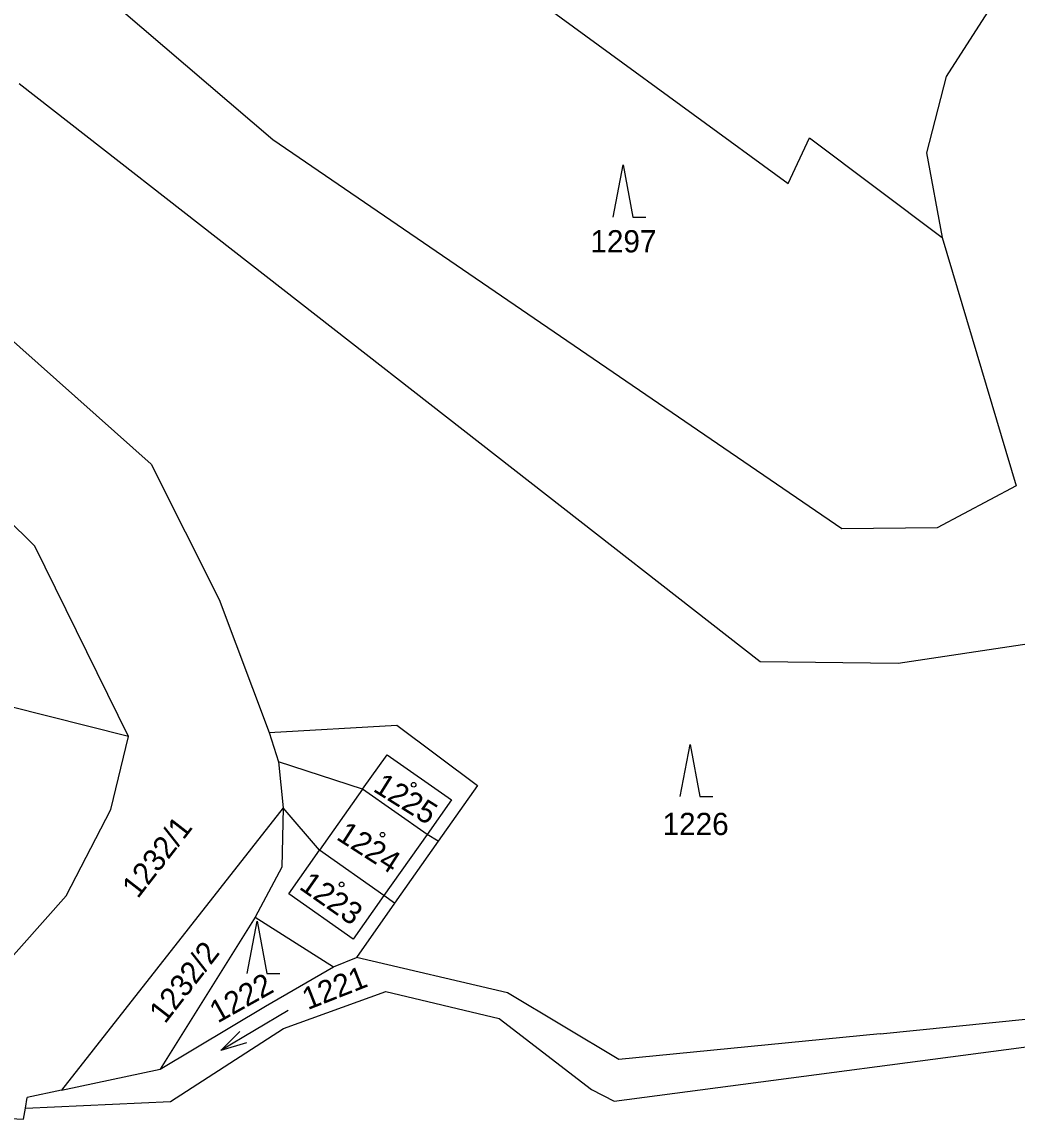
# Model space of a CAD drawing. Extents: x -670359 to -660124, y -978807 to -970072.
# Drawn here: x -669922.7 to -669846.5, y -978158.2 to -978074.2 of the extents above; entities that cross this region are included whole.
import ezdxf

# ---------------------------------------------------------------- set-up
doc = ezdxf.new("R2010")
doc.units = 0
for name, color, linetype in [('Hranice kat_území', 7, 'Continuous'), ('Hranice parcel', 7, 'Continuous'), ('Parcelní čísla', 7, 'Continuous'), ('Vnitřní kresba', 7, 'Continuous'), ('Značky budov', 7, 'Continuous'), ('Značky kultur', 7, 'Continuous')]:
    doc.layers.add(name, color=color, linetype=linetype)

msp = doc.modelspace()

# ---------------------------------------------------------------- linework, layer by layer
at = {"layer": 'Hranice kat_území'}
for points in [[(-669902.66, -978151.28), (-669894.83, -978148.43)], [(-669894.83, -978148.43), (-669886.17, -978150.51)], [(-669886.17, -978150.51), (-669879.09, -978155.94)], [(-669911.31, -978156.86), (-669902.66, -978151.28)], [(-669877.35, -978156.82), (-669839.43, -978151.83)], [(-669879.09, -978155.94), (-669877.35, -978156.82)], [(-669922.41, -978157.37), (-669911.31, -978156.86)], [(-669938.71, -978157.38), (-669922.55, -978158.2)], [(-669922.55, -978158.2), (-669922.41, -978157.37)]]:
    msp.add_lwpolyline(points, dxfattribs=at)
at = {"layer": 'Hranice parcel'}
for p, q in [((-669902.68, -978134.37), (-669919.64, -978156)), ((-669919.64, -978156), (-669912.09, -978154.39)), ((-669919.64, -978156), (-669922.27, -978156.56))]:
    msp.add_line(p, q, dxfattribs=at)
for points in [[(-669893.12, -978065.33), (-669864.05, -978086.6)], [(-669845.36, -978068.08), (-669851.96, -978078.41)], [(-669903.47, -978083.25), (-669915.09, -978073.32)], [(-669866.2, -978123.21), (-669922.9, -978078.96)], [(-669851.96, -978078.41), (-669853.46, -978084.23)], [(-669859.93, -978113.03), (-669903.47, -978083.25)], [(-669864.05, -978086.6), (-669862.41, -978083.09)], [(-669862.41, -978083.09), (-669852.25, -978090.72)], [(-669853.46, -978084.23), (-669852.25, -978090.72)], [(-669935.73, -978087.67), (-669912.8, -978108.06)], [(-669852.25, -978090.72), (-669846.6, -978109.74)], [(-669912.8, -978108.06), (-669907.59, -978118.42)], [(-669921.7, -978114.35), (-669926.19, -978109.93)], [(-669846.6, -978109.74), (-669852.64, -978112.95)], [(-669852.64, -978112.95), (-669859.93, -978113.03)], [(-669914.52, -978128.92), (-669921.7, -978114.35)], [(-669907.59, -978118.42), (-669903.75, -978128.6)], [(-669845.61, -978121.83), (-669855.63, -978123.32)], [(-669855.63, -978123.32), (-669866.2, -978123.21)], [(-669914.52, -978128.92), (-669929.83, -978125.06)], [(-669903.75, -978128.6), (-669893.98, -978128.04)], [(-669903.75, -978128.6), (-669903.05, -978130.85)], [(-669893.98, -978128.04), (-669887.81, -978132.66)], [(-669915.88, -978134.51), (-669914.52, -978128.92)], [(-669903.05, -978130.85), (-669902.68, -978134.37)], [(-669896.61, -978132.95), (-669903.05, -978130.85)], [(-669891.68, -978136.42), (-669896.61, -978132.95)], [(-669887.81, -978132.66), (-669890.82, -978136.94)], [(-669919.3, -978141.12), (-669915.88, -978134.51)], [(-669902.68, -978134.37), (-669902.79, -978138.93)], [(-669899.9, -978137.63), (-669902.68, -978134.37)], [(-669890.82, -978136.94), (-669894.16, -978141.67)], [(-669890.82, -978136.94), (-669891.68, -978136.42)], [(-669894.98, -978141.1), (-669899.9, -978137.63)], [(-669902.79, -978138.93), (-669904.82, -978142.75)], [(-669924.55, -978147), (-669919.3, -978141.12)], [(-669894.16, -978141.67), (-669894.98, -978141.1)], [(-669894.16, -978141.67), (-669897.09, -978145.83)], [(-669904.82, -978142.75), (-669912.09, -978154.39)], [(-669904.82, -978142.75), (-669898.85, -978146.56)], [(-669898.85, -978146.56), (-669897.09, -978145.83)], [(-669885.52, -978148.55), (-669897.09, -978145.83)], [(-669904.04, -978149.57), (-669898.85, -978146.56)], [(-669877.01, -978153.63), (-669885.52, -978148.55)], [(-669912.09, -978154.39), (-669904.04, -978149.57)], [(-669857.01, -978151.67), (-669845.64, -978150.52)], [(-669857.01, -978151.67), (-669877.01, -978153.63)], [(-669922.41, -978157.37), (-669922.27, -978156.56)]]:
    msp.add_lwpolyline(points, dxfattribs=at)
at = {"layer": 'Vnitřní kresba'}
for points in [[(-669896.61, -978132.95), (-669894.74, -978130.33)], [(-669894.74, -978130.33), (-669889.81, -978133.76)], [(-669896.61, -978132.95), (-669899.9, -978137.63)], [(-669889.81, -978133.76), (-669891.68, -978136.42)], [(-669891.68, -978136.42), (-669894.98, -978141.1)], [(-669902.25, -978140.97), (-669899.9, -978137.63)], [(-669897.33, -978144.44), (-669902.25, -978140.97)], [(-669894.98, -978141.1), (-669897.33, -978144.44)]]:
    msp.add_lwpolyline(points, dxfattribs=at)
at = {"layer": 'Značky budov'}
for centre in [(-669892.7, -978132.61), (-669895.09, -978136.43), (-669898.22, -978140.24)]:
    msp.add_circle(centre, 0.175, dxfattribs=at)
at = {"layer": 'Značky kultur'}
msp.add_line((-669902.303, -978149.885), (-669907.457, -978152.955), dxfattribs=at)
for points in [[(-669877.43, -978089.16), (-669876.68, -978085.16), (-669875.93, -978089.16), (-669874.93, -978089.16)], [(-669872.3, -978133.52), (-669871.55, -978129.52), (-669870.8, -978133.52), (-669869.8, -978133.52)], [(-669905.44, -978147.05), (-669904.69, -978143.05), (-669903.94, -978147.05), (-669902.94, -978147.05)], [(-669905.483, -978152.361), (-669907.457, -978152.955), (-669905.995, -978151.502)]]:
    msp.add_lwpolyline(points, dxfattribs=at)
for centre in [(-669892.7, -978132.61), (-669895.09, -978136.43), (-669898.22, -978140.24)]:
    msp.add_circle(centre, 0.175, dxfattribs=at)

# ---------------------------------------------------------------- texts
at = {"layer": 'Parcelní čísla'}
for s, p in [('1297', (-669879.18, -978091.86)), ('1226', (-669873.654, -978136.46))]:
    msp.add_text(s, height=1.7, dxfattribs=at).set_placement(p)
for s, rotation, p in [('1225', 328.03353, (-669895.891, -978133.056)), ('1232/1', 52.2, (-669913.815, -978141.387)), ('1224', 327.33909, (-669898.705, -978136.742)), ('1223', 324.94059, (-669901.546, -978140.534)), ('1232/2', 52.2, (-669911.732, -978150.971)), ('1222', 29.25594, (-669907.701, -978150.892)), ('1221', 21.47679, (-669900.807, -978149.868))]:
    msp.add_text(s, height=1.7, rotation=rotation, dxfattribs=at).set_placement(p)

doc.saveas('drawing.dxf')
